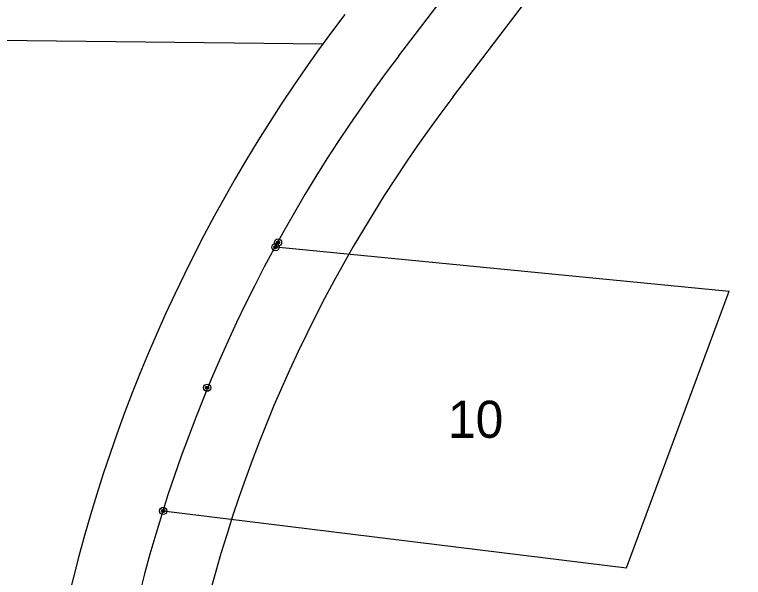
# Model space of a CAD drawing. Extents: x 1398271 to 1401121, y 1018936 to 1022764.
# Drawn here: x 1399686.3 to 1400039.7, y 1020616.3 to 1020889.4 of the extents above; entities that cross this region are included whole.
import ezdxf

# ---------------------------------------------------------------- set-up
doc = ezdxf.new("R2010")
doc.units = 0
for name, color, linetype in [('RD_EX_DV_Prop', 7, 'Continuous'), ('RD_EX_DV_PropPin', 7, 'Continuous'), ('RD_EX_DV_TX_Prop', 7, 'Continuous'), ('RD_EX_RW', 7, 'Continuous'), ('RD_HC_Cl', 7, 'Continuous'), ('RD_SMD_Locator', 7, 'Continuous')]:
    doc.layers.add(name, color=color, linetype=linetype)

msp = doc.modelspace()

# ---------------------------------------------------------------- linework, layer by layer
at = {"layer": 'RD_EX_DV_Prop'}
for p, q in [((1399835.71, 1020875.08), (1399340.79, 1020880.54)), ((1400032.69, 1020755.04), (1399812.8, 1020776.56)), ((1399982.95, 1020620.97), (1400032.74, 1020755.17)), ((1399758.35, 1020648.57), (1399982.95, 1020620.97))]:
    msp.add_line(p, q, dxfattribs=at)
at = {"layer": 'RD_EX_DV_PropPin'}
for p, q in [((1399812.06, 1020776.36), (1399812.06, 1020776.75)), ((1399812.1, 1020776.26), (1399812.1, 1020776.86)), ((1399812.13, 1020776.19), (1399812.13, 1020776.93)), ((1399812.17, 1020776.13), (1399812.17, 1020776.98)), ((1399812.2, 1020776.08), (1399812.2, 1020777.03)), ((1399812.24, 1020776.04), (1399812.24, 1020777.07)), ((1399812.27, 1020776.01), (1399812.27, 1020777.11)), ((1399812.31, 1020775.98), (1399812.31, 1020777.14)), ((1399812.34, 1020775.95), (1399812.34, 1020777.17)), ((1399812.38, 1020775.92), (1399812.38, 1020777.19)), ((1399812.41, 1020775.9), (1399812.41, 1020777.21)), ((1399812.45, 1020775.88), (1399812.45, 1020777.23)), ((1399812.48, 1020775.86), (1399812.48, 1020777.25)), ((1399812.52, 1020775.85), (1399812.52, 1020777.27)), ((1399812.55, 1020775.84), (1399812.55, 1020777.28)), ((1399812.59, 1020775.83), (1399812.59, 1020777.29)), ((1399812.62, 1020775.82), (1399812.62, 1020777.3)), ((1399812.66, 1020775.81), (1399812.66, 1020777.31)), ((1399812.69, 1020775.8), (1399812.69, 1020777.31)), ((1399812.73, 1020775.8), (1399812.73, 1020777.32)), ((1399812.76, 1020775.8), (1399812.76, 1020777.32)), ((1399812.8, 1020775.8), (1399812.8, 1020777.32)), ((1399812.83, 1020775.8), (1399812.83, 1020777.32)), ((1399812.87, 1020775.8), (1399812.87, 1020777.32)), ((1399812.9, 1020775.8), (1399812.9, 1020777.31)), ((1399812.94, 1020775.81), (1399812.94, 1020777.31)), ((1399812.97, 1020775.82), (1399812.97, 1020777.3)), ((1399813.01, 1020775.83), (1399813.01, 1020777.29)), ((1399813.04, 1020775.84), (1399813.04, 1020777.28)), ((1399813.08, 1020775.85), (1399813.08, 1020777.27)), ((1399813.11, 1020775.86), (1399813.11, 1020777.25)), ((1399813.15, 1020775.88), (1399813.15, 1020777.23)), ((1399813.18, 1020775.9), (1399813.18, 1020777.21)), ((1399813.22, 1020775.92), (1399813.22, 1020777.19)), ((1399813.25, 1020775.95), (1399813.25, 1020777.17)), ((1399813.29, 1020775.98), (1399813.29, 1020777.14)), ((1399813.32, 1020778.6), (1399813.32, 1020778.99)), ((1399813.32, 1020776.01), (1399813.32, 1020777.11)), ((1399813.35, 1020778.5), (1399813.35, 1020779.09)), ((1399813.36, 1020776.04), (1399813.36, 1020777.07)), ((1399813.39, 1020778.43), (1399813.39, 1020779.17)), ((1399813.39, 1020776.08), (1399813.39, 1020777.03)), ((1399813.42, 1020778.37), (1399813.42, 1020779.22)), ((1399813.43, 1020776.13), (1399813.43, 1020776.98)), ((1399813.46, 1020778.32), (1399813.46, 1020779.27)), ((1399813.46, 1020776.19), (1399813.46, 1020776.93)), ((1399813.49, 1020778.28), (1399813.49, 1020779.31)), ((1399813.5, 1020776.26), (1399813.5, 1020776.86)), ((1399813.53, 1020778.25), (1399813.53, 1020779.35)), ((1399813.53, 1020776.36), (1399813.53, 1020776.75)), ((1399813.56, 1020778.21), (1399813.56, 1020779.38)), ((1399813.6, 1020778.19), (1399813.6, 1020779.41)), ((1399813.63, 1020778.16), (1399813.63, 1020779.43)), ((1399813.67, 1020778.14), (1399813.67, 1020779.45)), ((1399813.7, 1020778.12), (1399813.7, 1020779.47)), ((1399813.74, 1020778.1), (1399813.74, 1020779.49)), ((1399813.77, 1020778.09), (1399813.77, 1020779.5)), ((1399813.81, 1020778.08), (1399813.81, 1020779.52)), ((1399813.84, 1020778.06), (1399813.84, 1020779.53)), ((1399813.88, 1020778.06), (1399813.88, 1020779.54)), ((1399813.91, 1020778.05), (1399813.91, 1020779.54)), ((1399813.95, 1020778.04), (1399813.95, 1020779.55)), ((1399813.98, 1020778.04), (1399813.98, 1020779.55)), ((1399814.02, 1020778.04), (1399814.02, 1020779.56)), ((1399814.05, 1020778.04), (1399814.05, 1020779.56)), ((1399814.09, 1020778.04), (1399814.09, 1020779.56)), ((1399814.12, 1020778.04), (1399814.12, 1020779.55)), ((1399814.16, 1020778.04), (1399814.16, 1020779.55)), ((1399814.19, 1020778.05), (1399814.19, 1020779.54)), ((1399814.23, 1020778.06), (1399814.23, 1020779.54)), ((1399814.26, 1020778.06), (1399814.26, 1020779.53)), ((1399814.3, 1020778.08), (1399814.3, 1020779.52)), ((1399814.33, 1020778.09), (1399814.33, 1020779.5)), ((1399814.37, 1020778.1), (1399814.37, 1020779.49)), ((1399814.4, 1020778.12), (1399814.4, 1020779.47)), ((1399814.44, 1020778.14), (1399814.44, 1020779.45)), ((1399814.47, 1020778.16), (1399814.47, 1020779.43)), ((1399814.51, 1020778.19), (1399814.51, 1020779.41)), ((1399814.54, 1020778.21), (1399814.54, 1020779.38)), ((1399814.58, 1020778.25), (1399814.58, 1020779.35)), ((1399814.61, 1020778.28), (1399814.61, 1020779.31)), ((1399814.65, 1020778.32), (1399814.65, 1020779.27)), ((1399814.68, 1020778.37), (1399814.68, 1020779.22)), ((1399814.72, 1020778.43), (1399814.72, 1020779.17)), ((1399814.75, 1020778.5), (1399814.75, 1020779.09)), ((1399814.79, 1020778.6), (1399814.79, 1020778.99)), ((1399779.24, 1020707.75), (1399779.24, 1020709.02)), ((1399779.28, 1020707.73), (1399779.28, 1020709.04)), ((1399779.31, 1020707.71), (1399779.31, 1020709.06)), ((1399779.35, 1020707.69), (1399779.35, 1020709.08)), ((1399779.38, 1020707.68), (1399779.38, 1020709.09)), ((1399779.42, 1020707.67), (1399779.42, 1020709.11)), ((1399779.45, 1020707.65), (1399779.45, 1020709.12)), ((1399779.49, 1020707.64), (1399779.49, 1020709.13)), ((1399779.52, 1020707.64), (1399779.52, 1020709.13)), ((1399779.56, 1020707.63), (1399779.56, 1020709.14)), ((1399779.59, 1020707.63), (1399779.59, 1020709.14)), ((1399779.63, 1020707.63), (1399779.63, 1020709.15)), ((1399779.66, 1020707.62), (1399779.66, 1020709.15)), ((1399779.7, 1020707.63), (1399779.7, 1020709.15)), ((1399779.73, 1020707.63), (1399779.73, 1020709.14)), ((1399779.77, 1020707.63), (1399779.77, 1020709.14)), ((1399779.8, 1020707.64), (1399779.8, 1020709.13)), ((1399779.84, 1020707.64), (1399779.84, 1020709.13)), ((1399779.87, 1020707.65), (1399779.87, 1020709.12)), ((1399779.91, 1020707.67), (1399779.91, 1020709.11)), ((1399779.94, 1020707.68), (1399779.94, 1020709.09)), ((1399779.98, 1020707.69), (1399779.98, 1020709.08)), ((1399780.01, 1020707.71), (1399780.01, 1020709.06)), ((1399780.05, 1020707.73), (1399780.05, 1020709.04)), ((1399780.08, 1020707.75), (1399780.08, 1020709.02)), ((1399778.93, 1020708.19), (1399778.93, 1020708.58)), ((1399778.96, 1020708.09), (1399778.96, 1020708.68)), ((1399779, 1020708.02), (1399779, 1020708.76)), ((1399779.03, 1020707.96), (1399779.03, 1020708.81)), ((1399779.07, 1020707.91), (1399779.07, 1020708.86)), ((1399779.1, 1020707.87), (1399779.1, 1020708.9)), ((1399779.14, 1020707.83), (1399779.14, 1020708.94)), ((1399779.17, 1020707.8), (1399779.17, 1020708.97)), ((1399779.21, 1020707.78), (1399779.21, 1020709)), ((1399780.12, 1020707.78), (1399780.12, 1020709)), ((1399780.15, 1020707.8), (1399780.15, 1020708.97)), ((1399780.19, 1020707.83), (1399780.19, 1020708.94)), ((1399780.22, 1020707.87), (1399780.22, 1020708.9)), ((1399780.26, 1020707.91), (1399780.26, 1020708.86)), ((1399780.29, 1020707.96), (1399780.29, 1020708.81)), ((1399780.33, 1020708.02), (1399780.33, 1020708.76)), ((1399780.36, 1020708.09), (1399780.36, 1020708.68)), ((1399780.4, 1020708.19), (1399780.4, 1020708.58)), ((1399757.72, 1020648.14), (1399757.72, 1020648.99)), ((1399757.75, 1020648.09), (1399757.75, 1020649.04)), ((1399757.79, 1020648.05), (1399757.79, 1020649.08)), ((1399757.82, 1020648.01), (1399757.82, 1020649.12)), ((1399757.86, 1020647.98), (1399757.86, 1020649.15)), ((1399757.89, 1020647.96), (1399757.89, 1020649.18)), ((1399757.93, 1020647.93), (1399757.93, 1020649.2)), ((1399757.96, 1020647.91), (1399757.96, 1020649.22)), ((1399758, 1020647.89), (1399758, 1020649.24)), ((1399758.03, 1020647.87), (1399758.03, 1020649.26)), ((1399758.07, 1020647.86), (1399758.07, 1020649.27)), ((1399758.1, 1020647.85), (1399758.1, 1020649.29)), ((1399758.14, 1020647.83), (1399758.14, 1020649.3)), ((1399758.17, 1020647.83), (1399758.17, 1020649.31)), ((1399758.21, 1020647.82), (1399758.21, 1020649.31)), ((1399758.24, 1020647.81), (1399758.24, 1020649.32)), ((1399758.28, 1020647.81), (1399758.28, 1020649.32)), ((1399758.31, 1020647.81), (1399758.31, 1020649.33)), ((1399758.35, 1020647.8), (1399758.35, 1020649.33)), ((1399758.38, 1020647.81), (1399758.38, 1020649.33)), ((1399758.42, 1020647.81), (1399758.42, 1020649.32)), ((1399758.45, 1020647.81), (1399758.45, 1020649.32)), ((1399758.49, 1020647.82), (1399758.49, 1020649.31)), ((1399758.52, 1020647.83), (1399758.52, 1020649.31)), ((1399758.56, 1020647.83), (1399758.56, 1020649.3)), ((1399758.59, 1020647.85), (1399758.59, 1020649.29)), ((1399758.63, 1020647.86), (1399758.63, 1020649.27)), ((1399758.66, 1020647.87), (1399758.66, 1020649.26)), ((1399758.7, 1020647.89), (1399758.7, 1020649.24)), ((1399758.73, 1020647.91), (1399758.73, 1020649.22)), ((1399758.77, 1020647.93), (1399758.77, 1020649.2)), ((1399758.8, 1020647.96), (1399758.8, 1020649.18)), ((1399758.84, 1020647.98), (1399758.84, 1020649.15)), ((1399758.87, 1020648.01), (1399758.87, 1020649.12)), ((1399758.91, 1020648.05), (1399758.91, 1020649.08)), ((1399758.94, 1020648.09), (1399758.94, 1020649.04)), ((1399758.98, 1020648.14), (1399758.98, 1020648.99)), ((1399757.61, 1020648.37), (1399757.61, 1020648.76)), ((1399757.65, 1020648.27), (1399757.65, 1020648.86)), ((1399757.68, 1020648.2), (1399757.68, 1020648.94)), ((1399759.01, 1020648.2), (1399759.01, 1020648.94)), ((1399759.05, 1020648.27), (1399759.05, 1020648.86)), ((1399759.08, 1020648.37), (1399759.08, 1020648.76))]:
    msp.add_line(p, q, dxfattribs=at)
for centre, radius in [((1399814.05, 1020778.8), 1.75), ((1399812.8, 1020776.56), 1.75), ((1399812.8, 1020776.56), 0.761), ((1399814.05, 1020778.8), 0.761), ((1399779.66, 1020708.39), 1.75), ((1399779.66, 1020708.39), 0.761), ((1399758.35, 1020648.57), 1.75), ((1399758.35, 1020648.57), 0.761)]:
    msp.add_circle(centre, radius, dxfattribs=at)
at = {"layer": 'RD_EX_RW'}
msp.add_line((1399898.85, 1020849.39), (1399957.28, 1020926.07), dxfattribs=at)
for radius in [754.84, 688.84]:
    msp.add_arc((1400446.73, 1020431.86), radius, 142.68944, 193.74255, dxfattribs=at)
at = {"layer": 'RD_HC_Cl'}
msp.add_line((1399872.6, 1020869.39), (1400252.64, 1021368.08), dxfattribs=at)
msp.add_arc((1400446.73, 1020431.86), 721.84, 142.68944, 193.74255, dxfattribs=at)
at = {"layer": 'RD_SMD_Locator'}
for centre in [(1399812.8, 1020776.56), (1399814.05, 1020778.8), (1399779.66, 1020708.39), (1399758.35, 1020648.57)]:
    msp.add_circle(centre, 0.15, dxfattribs=at)

# ---------------------------------------------------------------- texts
at = {"layer": 'RD_EX_DV_TX_Prop'}
msp.add_text('10', height=18, dxfattribs=at).set_placement((1399896.46, 1020684.05))

doc.saveas('drawing.dxf')
